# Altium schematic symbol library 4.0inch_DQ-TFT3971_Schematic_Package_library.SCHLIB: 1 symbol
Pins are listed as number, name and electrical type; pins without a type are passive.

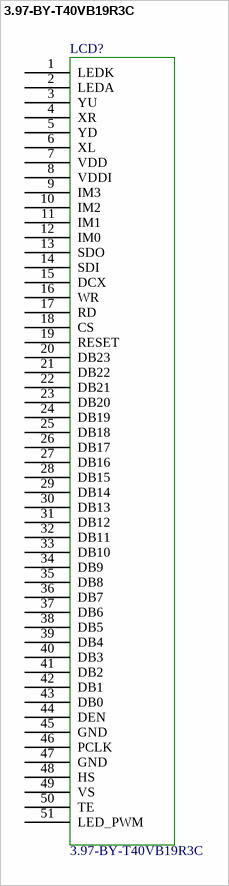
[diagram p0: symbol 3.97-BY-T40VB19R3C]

## 3.97-BY-T40VB19R3C
designator LCD?
footprint 3.97-BY-T40VB19R3C
pins: 1 LEDK, 2 LEDA, 3 YU, 4 XR, 5 YD, 6 XL, 7 VDD, 8 VDDI, 9 IM3, 10 IM2, 11 IM1, 12 IM0, 13 SDO, 14 SDI, 15 DCX, 16 WR, 17 RD, 18 CS, 19 RESET, 20 DB23, 21 DB22, 22 DB21, 23 DB20, 24 DB19, 25 DB18, 26 DB17, 27 DB16, 28 DB15, 29 DB14, 30 DB13, 31 DB12, 32 DB11, 33 DB10, 34 DB9, 35 DB8, 36 DB7, 37 DB6, 38 DB5, 39 DB4, 40 DB3, 41 DB2, 42 DB1, 43 DB0, 44 DEN, 45 GND, 46 PCLK, 47 GND, 48 HS, 49 VS, 50 TE, 51 LED_PWM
